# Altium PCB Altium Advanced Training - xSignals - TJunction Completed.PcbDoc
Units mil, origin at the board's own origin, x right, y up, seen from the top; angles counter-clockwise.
Board outline 4055.12 x 2100 mil, 3 copper layers (Top Layer, GND, Bottom Layer), stack 68.617 mil thick; 14 components, 11 nets, 32 pads, 2 vias.
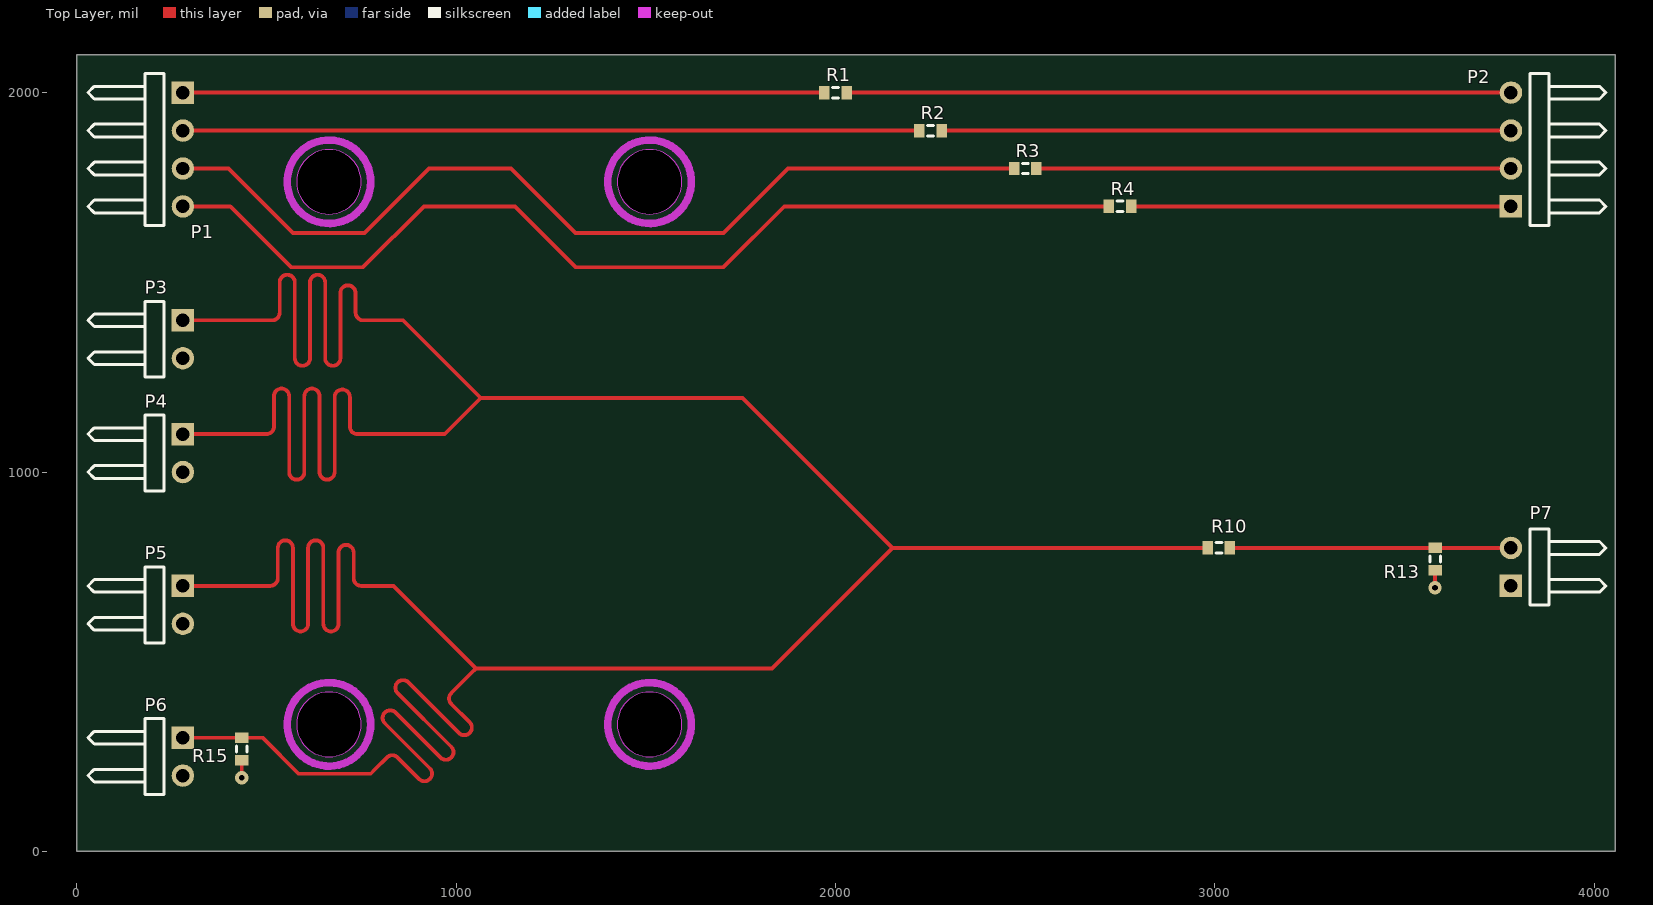
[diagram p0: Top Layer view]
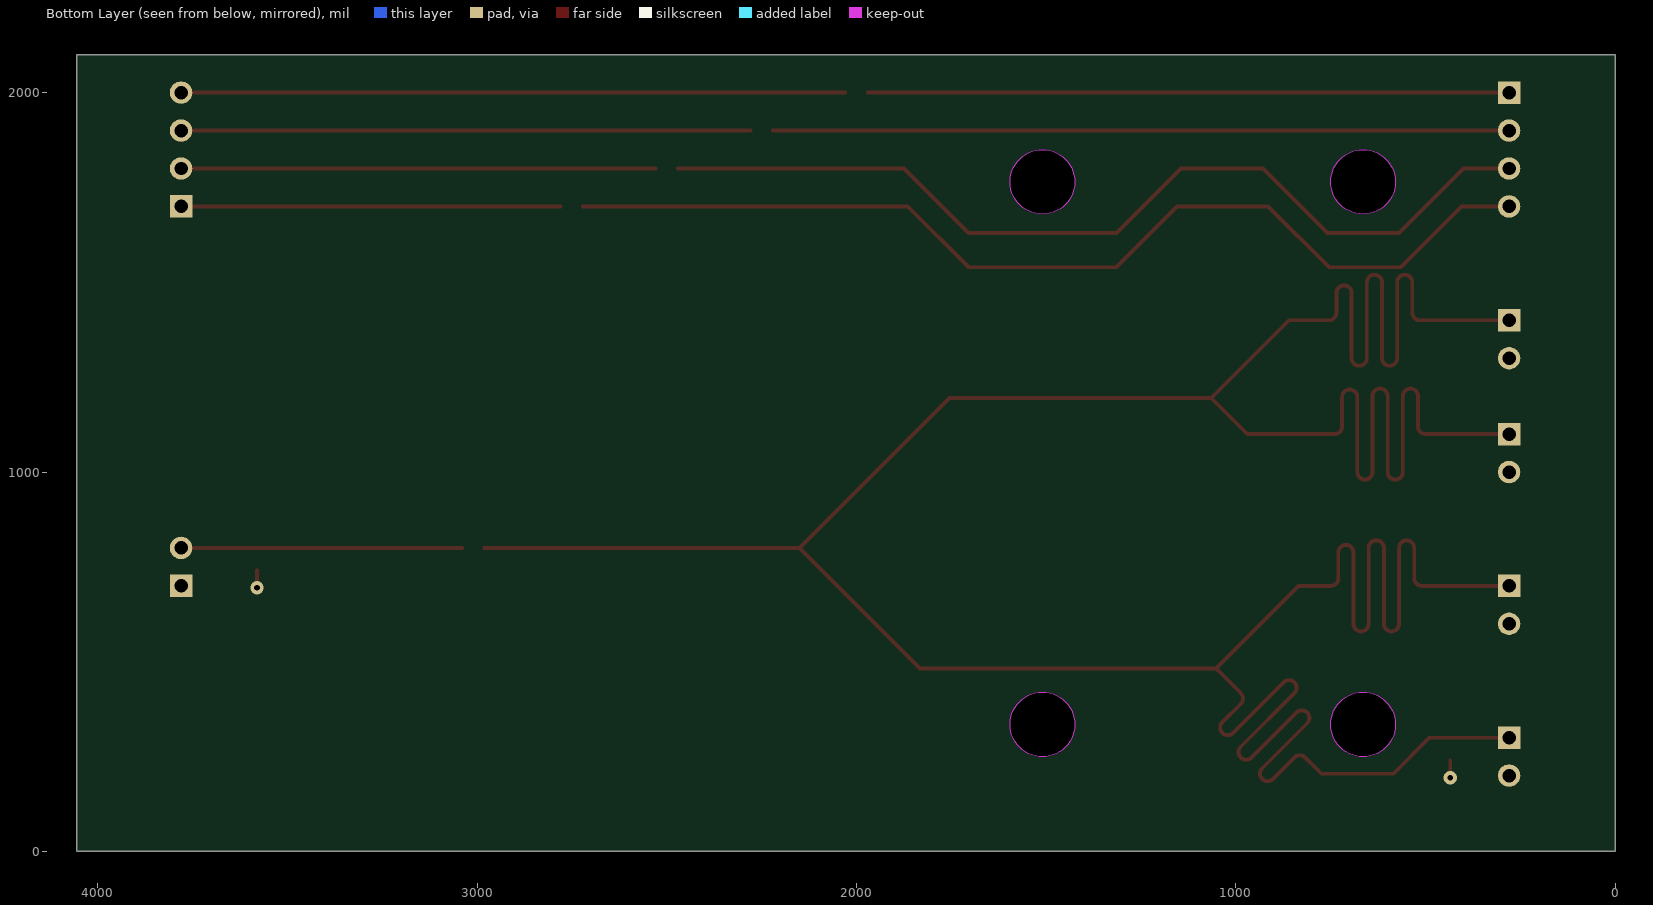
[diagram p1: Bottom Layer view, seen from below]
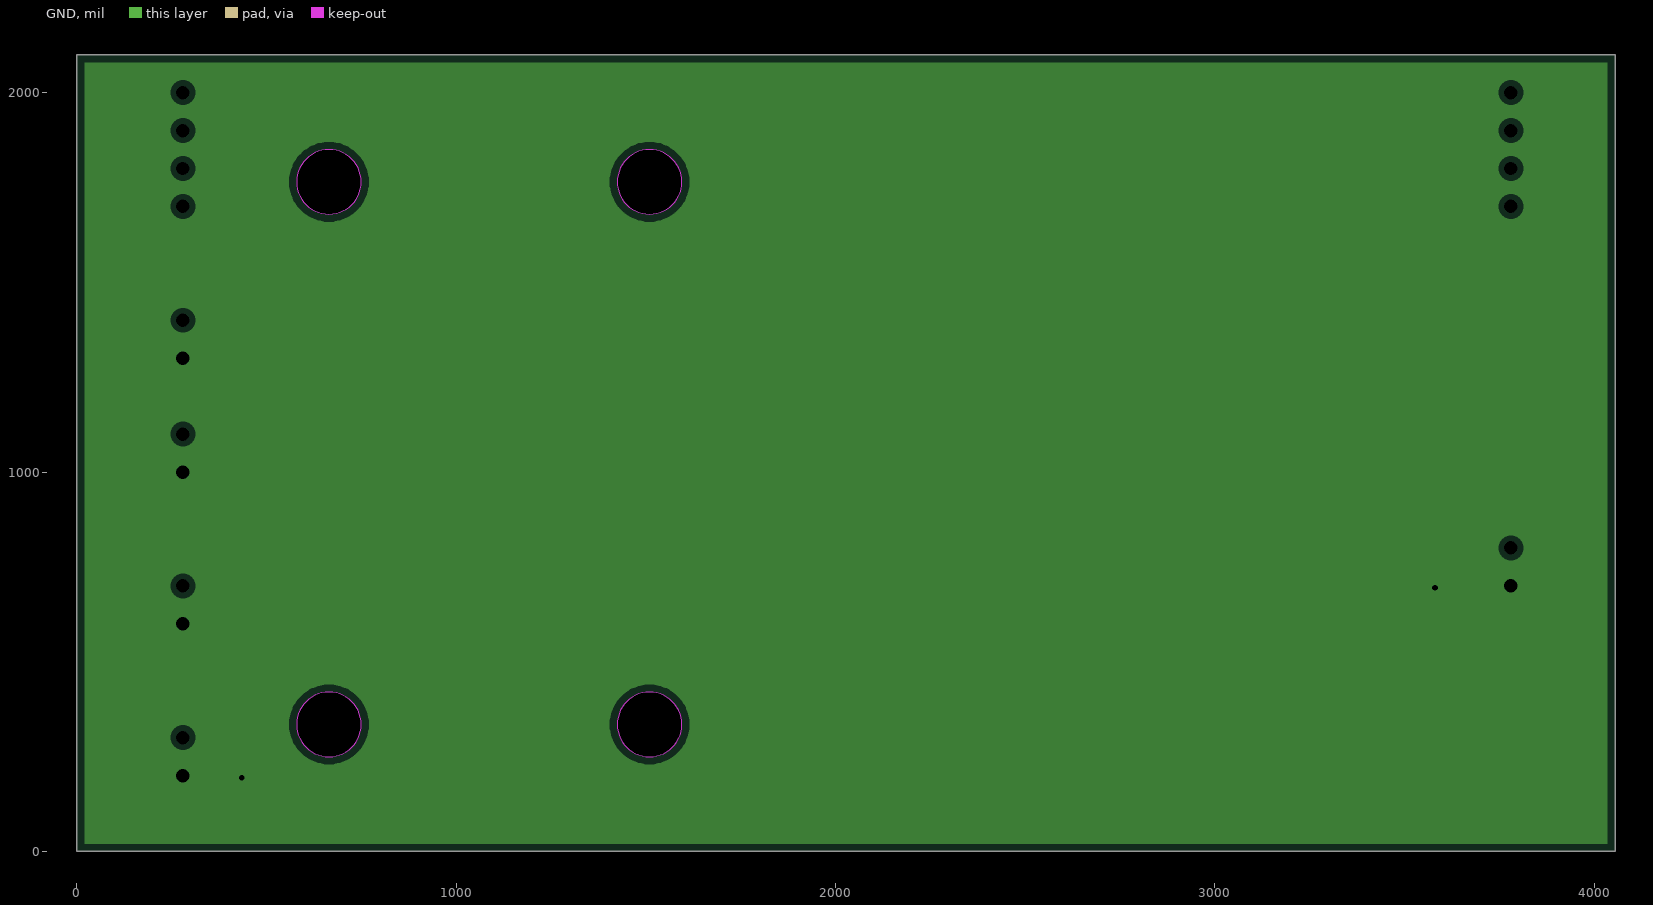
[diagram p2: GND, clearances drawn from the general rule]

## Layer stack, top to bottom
Top Solder: solder mask 0.4, Solder Resist, Dk 3.5
Top Layer: signal copper 1.4
Dielectric1: core 59.4, FR-4, Dk 4
GND: plane copper 1.417, net GND
Dielectric 2: prepreg 5, Dk 4.2
Bottom Layer: signal copper 1.4
Bottom Solder: solder mask 0.4, Solder Resist, Dk 3.5

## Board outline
0,0 4055.12,0 4055.12,2100 0,2100
cut-out: 579.65,334.79 ccw(c664.79,334.79) 664.79,249.65 ccw(c664.79,334.79) 749.94,334.79 ccw(c664.79,334.79) 664.79,419.94 ccw(c664.79,334.79)
cut-out: 579.65,1764.79 ccw(c664.79,1764.79) 664.79,1679.65 ccw(c664.79,1764.79) 749.94,1764.79 ccw(c664.79,1764.79) 664.79,1849.94 ccw(c664.79,1764.79)
cut-out: 1424.65,334.79 ccw(c1509.79,334.79) 1509.79,249.65 ccw(c1509.79,334.79) 1594.94,334.79 ccw(c1509.79,334.79) 1509.79,419.94 ccw(c1509.79,334.79)
cut-out: 1424.65,1764.79 ccw(c1509.79,1764.79) 1509.79,1679.65 ccw(c1509.79,1764.79) 1594.94,1764.79 ccw(c1509.79,1764.79) 1509.79,1849.94 ccw(c1509.79,1764.79)

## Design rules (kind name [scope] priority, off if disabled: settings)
AcuteAngle [All] p1: minimum=5.50000000000000E+0001 checktracksonly=FALSE
AssemblyTestPointUsage [All] p1 off:
AssemblyTestpoint [All] p1 off: testpointundercomponent=TRUE minsize=40 maxsize=100 preferedsize=60 minholesize=0 maxholesize=40 preferedholesize=32 testpointgrid=1 usegrid=TRUE gridtolerance=0.01 allowsidetop=TRUE allowsidebottom=TRUE
BoardOutlineClearance [All] p1: gap=10 ignorepadtopadclearanceinfootprint=FALSE except(0: Arc-SplitContinuation Track-SplitContinuation SMDPad-SplitContinuation THPad-SplitContinuation Via-SplitContinuation Fill-SplitContinuation Poly-SplitContinuation Region-SplitContinuation Text-SplitContinuation)
Clearance [All] p1: gap=8 ignorepadtopadclearanceinfootprint=FALSE except(0: Arc-Hole Track-Hole SMDPad-Hole THPad-Hole Via-Hole Fill-Hole Poly-Hole Region-Hole Text-Hole)
FabricationTestPointUsage [All] p1 off: valid=0 allowmultiple=FALSE
FabricationTestpoint [(IsPad And (OnTopLayer Or OnBottomLayer))] p1 off: side=3 testpointundercomponent=TRUE minsize=40 maxsize=100 preferedsize=60 minholesize=0 maxholesize=40 preferedholesize=32 testpointgrid=1 allowsidetop=TRUE allowsidebottom=TRUE usegrid=TRUE gridtolerance=0.01
Height [All] p1: minheight=0 maxheight=1500 prefheight=500
HoleSize [All] p1: absolutevalues=TRUE maxlimit=200 minlimit=10 maxpercent=80.000 minpercent=20.000
HoleToHoleClearance [All] p1: gap=1 allowstackedmicrovias=FALSE
Length Length_TJunction [InxSignalClass('T-Junction')] p1: maxlimit=4100 minlimit=3900
Length Length_Series-Term [InxSignalClass('Series-Term')] p2: maxlimit=3855 minlimit=3845
MatchedLengths MatchedLengths_TJunction [InxSignalClass('T-Junction')] p1: tolerance=10 checknetsindiffpair=FALSE checkdiffpairvsdiffpair=TRUE checkxsignals=TRUE checkothers=TRUE
MinimumAnnularRing [All] p1: minimumring=5
MinimumSolderMaskSliver [All] p1: minsoldermaskwidth=3
NetAntennae [All] p1: netantennaetolerance=5
PlaneClearance [All] p1: clearance=15
PlaneConnect [All] p1: planeconnectstyle=Relief reliefexpansion=15 reliefentries=4 reliefconductorwidth=8 reliefairgap=8
PolygonConnect [All] p1: connectstyle=Relief reliefconductorwidth=8 reliefentries=4 polygonreliefangle="90 Angle" airgapwidth=10
RoutingTopology RoutingTopology_TJUNCT [InNet('TJUNCT')] p1: topology=Starburst
RoutingTopology [All] p2: topology=Shortest
RoutingVias [All] p1: holewidth=10 width=20 viastyle="Through Hole" minholewidth=10 minwidth=20 maxholewidth=30 maxwidth=40
SilkToSilkClearance [All] p1: silktosilkclearance=1
SilkToSolderMaskClearance SilkscreenOverComponentPads [IsPad] p1: minsilkscreentomaskgap=2 clearancetoexposedcopper=TRUE
SolderMaskExpansion [All] p1: expansion=1 istentingtop=FALSE
Width [All] p1: maxlimit=200 minlimit=8 preferedwidth=10
16 further rules are at their usual default settings.

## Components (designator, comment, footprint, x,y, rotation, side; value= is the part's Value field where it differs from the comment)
P1 "Header 4H" HDR1X4H 280,2000 r270 top
P2 "Header 4H" HDR1X4H 3780,1700 r90 top
P3 "Header 2H" HDR1X2H 280,1400 r270 top
P4 "Header 2H" HDR1X2H 280,1100 r270 top
P5 "Header 2H" HDR1X2H 280,700 r270 top
P6 "Header 2H" HDR1X2H 280,300 r270 top
P7 "Header 2H" HDR1X2H 3780,700 r90 top
R1 "Res3" J1-0603 2000,2000 r180 top
R2 "Res3" J1-0603 2250,1900 r180 top
R3 "Res3" J1-0603 2500,1800 r180 top
R4 "Res3" J1-0603 2750,1700 r180 top
R10 "Res3" J1-0603 3010,800 r180 top
R13 "Res3" J1-0603 3580,770.47 r90 top
R15 "Res3" J1-0603 435,270 r90 top

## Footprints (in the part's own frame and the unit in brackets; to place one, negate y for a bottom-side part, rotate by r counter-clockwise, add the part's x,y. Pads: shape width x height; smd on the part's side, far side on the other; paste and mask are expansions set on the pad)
HDR1X2H [mm] "Connector; Header; 2 Position; Right Angle"
  rect 1.5x1.5 hole 0.9: 1(0,0)
  round 1.5 hole 0.9: 2(2.54,0)
  silkscreen extent -1.27,-6.35 3.81,-1.27
HDR1X4H [mm] "Connector; Header; 4 Position; Right Angle"
  rect 1.5x1.5 hole 0.9: 1(0,0)
  round 1.5 hole 0.9: 2(2.54,0) 3(5.08,0) 4(7.62,0)
  silkscreen extent -1.27,-6.35 8.89,-1.27
J1-0603 [mm] "Chip Resistor, Body 1.6x0.8mm, IPC High Density"
  rect 0.7x0.9 smd: 1(-0.75,0) 2(0.75,0)
  silkscreen extent -0.2,-0.35 0.2,0.35, body extent -0.85,-0.48 0.85,0.48, height 0.9

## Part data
P1 P2: "Header, 4-Pin, Right Angle"
P3 P4 P5 P6 P7: "Header, 2-Pin, Right Angle"
R1 R2 R3 R4 R10 R13 R15: "Resistor"

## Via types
v1: diameter 35, hole 15, Top Layer to Bottom Layer, 2 vias

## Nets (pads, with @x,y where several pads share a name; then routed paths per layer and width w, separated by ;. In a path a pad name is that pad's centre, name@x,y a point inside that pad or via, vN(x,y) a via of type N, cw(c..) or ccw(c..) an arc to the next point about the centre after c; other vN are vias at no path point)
BUS1: P1.1 R1.2 | length 1690.5
  Top Layer w10: P1.1 1050,2000 1510,2000 1569.77,2000 R1.2
BUS2: P1.2 R2.2 | length 1940.5
  Top Layer w10: P1.2 R2.2
BUS3: P1.3 R3.2 | length 2472.1
  Top Layer w10: P1.3 400,1800 570,1630 758.75,1630 928.75,1800 1145,1800 1315,1630 1705,1630 1875,1800 1937.5,1800 2235,1800 2285,1800 R3.2
BUS4: P1.4 R4.2 | length 2705.6
  Top Layer w10: P1.4 405,1700 565,1540 755,1540 915,1700 985,1700 1140,1700 1155,1700 1315,1540 1705,1540 1865,1700 2045,1700 2315,1700 R4.2
GND: P3.2 P4.2 P5.2 P6.2 P7.1 R13.1 R15.1 | length 91.9
  Top Layer w10: v1(435,194.53) R15.1 ; v1(3580,695) R13.1
OBUS1: P2.4 R1.1 | length 1750.5
  Top Layer w10: R1.1 2897.82,2000 P2.4
OBUS2: P2.3 R2.1 | length 1500.5
  Top Layer w10: R2.1 2540,1900 2720,1900 3225,1900 P2.3
OBUS3: P2.2 R3.1 | length 1250.5
  Top Layer w10: R3.1 P2.2
OBUS4: P2.1 R4.1 | length 1000.5
  Top Layer w10: R4.1 3271.89,1700 P2.1
TJSOURCE: P7.2 R10.1 R13.2 | length 740.5
  Top Layer w10: R10.1 R13.2 P7.2
TJUNCT: P3.1 P4.1 P5.1 P6.1 R10.2 R15.2 | length 11006.3
  Top Layer w10: P6.1 434.53,300 R15.2 435.47,300 490,300 585,205 775,205 785.78,215.78 817.6,247.6 cw(c831.75,233.46) 845.89,247.6 902.46,191.03 ccw(c916.6,205.18) 930.74,191.03 ccw(c916.6,205.18) 930.74,219.32 812.14,337.92 cw(c826.28,352.06) 812.14,366.2 cw(c826.28,352.06) 840.43,366.2 959.02,247.6 ccw(c973.17,261.75) 987.31,247.6 ccw(c973.17,261.75) 987.31,275.89 845.89,417.31 cw(c860.03,431.45) 845.89,445.59 cw(c860.03,431.45) 874.17,445.59 1007.21,312.56 ccw(c1021.35,326.7) 1035.49,312.56 ccw(c1021.35,326.7) 1035.49,340.84 987.31,389.02 cw(c1001.45,403.17) 987.31,417.31 1040,470 1052.5,482.5 ; P5.1 505,700 510,700 ccw(c510,720) 530,720 530,800 cw(c550,800) 570,800 570,600 ccw(c590,600) 610,600 610,800 cw(c630,800) 650,800 650,600 ccw(c670,600) 690,600 690,787.97 cw(c710,787.97) 730,787.97 730,720 ccw(c750,720) 750,700 795,700 835,700 1052.5,482.5 ; P4.1 495,1100 500,1100 ccw(c500,1120) 520,1120 520,1200 cw(c540,1200) 560,1200 560,1000 ccw(c580,1000) 600,1000 600,1200 cw(c620,1200) 640,1200 640,1000 ccw(c660,1000) 680,1000 680,1197.29 cw(c700,1197.29) 720,1197.29 720,1120 ccw(c740,1120) 740,1100 940,1100 970,1100 1065,1195 ; P3.1 510,1400 515,1400 ccw(c515,1420) 535,1420 535,1500 cw(c555,1500) 575,1500 575,1300 ccw(c595,1300) 615,1300 615,1500 cw(c635,1500) 655,1500 655,1300 ccw(c675,1300) 695,1300 695,1472 cw(c715,1472) 735,1472 735,1420 ccw(c755,1420) 755,1400 785,1400 860,1400 1065,1195 ; R10.2 2150,800 ; 1052.5,482.5 1832.5,482.5 2150,800 ; 1065,1195 1755,1195 2150,800

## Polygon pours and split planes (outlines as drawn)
GND on GND (split plane): 4035.02,20.1 20.1,20.1 20.1,2079.9 4035.02,2079.9

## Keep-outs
Top Layer:
  circle w20: c665,335 r110
  circle w20: c665,1765 r110
  circle w20: c1510,335 r110
  circle w20: c1510,1765 r110

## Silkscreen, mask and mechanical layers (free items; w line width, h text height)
Top Overlay:
  text "Altium Advanced Training: '.Pcb_File_Name_No_Path'" at 15,-251.68 h100
Mechanical 1:
  drawing of 211 lines, arcs and shapes, not listed
  text "Layer" at -5222.5,-212.5 h60
  text "Name" at -4874.26,-212.5 h60
  text "Material" at -4109.54,-212.5 h60
  text "Thickness" at -3447.08,-212.5 h60
  text "Constant" at -2933.16,-212.5 h60
  text "Board Layer Stack" at -2440.37,-212.5 h60
  text "Top Overlay" at -4874.26,-332.5 h60
  text "Top Solder" at -4874.26,-452.5 h60
  text "Solder Resist" at -4109.54,-452.5 h60
  text "0,40mil" at -3447.08,-452.5 h60
  text "3.5" at -2933.16,-452.5 h60
  text "1" at -5222.5,-572.5 h60
  text "Top Layer" at -4874.26,-572.5 h60
  text "1,40mil" at -3447.08,-572.5 h60
  text "Dielectric1" at -4874.26,-692.5 h60
  text "FR-4" at -4109.54,-692.5 h60
  text "59,40mil" at -3447.08,-692.5 h60
  text "4" at -2933.16,-692.5 h60
  text "2" at -5222.5,-812.5 h60
  text "GND" at -4874.26,-812.5 h60
  text "1,42mil" at -3447.08,-812.5 h60
  text "Dielectric 2" at -4874.26,-932.5 h60
  text "5,00mil" at -3447.08,-932.5 h60
  text "4.2" at -2933.16,-932.5 h60
  text "3" at -5222.5,-1052.5 h60
  text "Bottom Layer" at -4874.26,-1052.5 h60
  text "1,40mil" at -3447.08,-1052.5 h60
  text "Bottom Solder" at -4874.26,-1172.5 h60
  text "Solder Resist" at -4109.54,-1172.5 h60
  text "0,40mil" at -3447.08,-1172.5 h60
  text "3.5" at -2933.16,-1172.5 h60
  text "Bottom Overlay" at -4874.26,-1292.5 h60
Mechanical 16:
  lines w5: -5810.13,-1827.43 -5610.13,-1827.43 ; -5810.13,547.57 -5610.13,547.57 ; -5810.13,2922.57 -5610.13,2922.57 ; -3310.13,-4202.43 -3310.13,-4002.43 ; -3310.13,5097.57 -3310.13,5297.57 ; -810.13,-4202.43 -810.13,-4002.43 ; -810.13,5097.57 -810.13,5297.57 ; 1536.87,-4002.43 1536.87,-3207.43 ; 1689.87,-4202.43 1689.87,-4002.43 ; 1689.87,5097.57 1689.87,5297.57 ; 3089.87,-3207.43 1536.87,-3207.43 ; 3089.87,-2934.43 1536.87,-2934.43 1536.87,-3207.43 ; 4189.87,-4202.43 4189.87,-4002.43 ; 4189.87,5097.57 4189.87,5297.57 ; 4489.87,-3702.43 8989.87,-3702.43 ; 4489.87,-3402.43 8989.87,-3402.43 ; 4489.87,-3102.43 5989.87,-3102.43 ; 5989.72,-4002.28 5989.72,-3402.28 5989.72,-2802.28 8989.72,-2802.28 8989.72,-4002.28 ; 5989.87,-2802.43 4489.87,-2802.43 ; 6613.21,-4202.75 6613.21,-4002.75 ; 6689.87,-4202.43 6689.87,-4002.43 ; 6689.87,5097.57 6689.87,5297.57 ; 7259.72,-4002.28 7259.72,-3702.28 ; 8089.72,-4002.28 8089.72,-3402.28 ; 8989.87,-1827.43 9189.87,-1827.43 ; 8989.87,547.57 9189.87,547.57 ; 8989.87,2922.57 9189.87,2922.57 ; 4489.87,-4002.43 4489.87,-2802.43 ; 4489.87,-4002.43 8989.87,-4002.43 ; 4489.87,-4002.43 3089.87,-4002.43 3089.87,-2802.43 4489.87,-2802.43 ; 8989.87,-4002.43 8989.87,5097.57 -5610.13,5097.57 -5610.13,-4002.43 8989.87,-4002.43 ; -5810.13,-4202.43 -5810.13,5297.57 9189.87,5297.57 9189.87,-4202.43 -5810.13,-4202.43
  lines w10: 6539.87,4817.57 6539.87,4892.57 6539.87,4957.57 6539.87,5032.57 6539.87,5097.57 ; 6540,4817.57 8989.87,4817.57 ; 6540,4892.57 8989.87,4892.57 8989.87,5032.57 ; 6540,4957.57 8989.87,4957.57 ; 6540,5032.57 8989.87,5032.57 ; 6540,5097.57 8989.87,5097.57 8989.87,5032.57 ; 6684.87,4817.76 6684.87,5032.57 ; 7014.87,4817.76 7014.87,5032.57 ; 8419.87,4817.76 8419.87,5032.57 ; 8689.87,4817.76 8689.87,5032.57
  text "1" at -4578.79,5167.57 h70
  text "2" at -2083.13,5167.57 h70
  text "3" at 406.21,5167.57 h70
  text "4" at 2912.88,5167.57 h70
  text "5" at 5411.87,5167.57 h70
  text "6" at 7916.87,5167.57 h70
  text "REVISIONS" at 7642,5051.76 h30
  text "DESCRIPTION" at 7630,4980.76 h30
  text "REV" at 6564.87,4977.57 h30
  text "ECO#/ECR#" at 6724.87,4977.57 h30
  text "APPROV" at 8454.87,4977.57 h30
  text "DATE" at 8794.87,4977.57 h30
  text "01" at 6584.87,4912.57 h30
  text "INITIAL RELEASE" at 7054.87,4912.57 h30
  text "10/31/11" at 8734.87,4912.57 h30
  text "A" at -5735.13,4024.57 h70
  text "A" at 9064.87,4024.57 h70
  text "B" at -5735.13,1644.57 h70
  text "B" at 9064.87,1644.57 h70
  text "C" at -5735.13,-730.43 h70
  text "C" at 9064.87,-730.43 h70
  text "ENGINEER:" at 4539.87,-2902.43 h45
  text "TITLE:" at 6039.72,-2902.28 h45
  text "<YOUR NAME>" at 4646.87,-3053.43 h80
  text "Company" at 3158,-3074.24 h140
  text "D" at -5735.13,-3100.43 h70
  text "D" at 9064.87,-3100.43 h70
  text "PCB DESIGNER:" at 4539.87,-3197.43 h45
  text "UNLESS OTHERWISE SPECIFIED" at 1626.87,-3313.43 h55.31
  text "<YOUR NAME>" at 4644.87,-3376.43 h80
  text "DIMINSIONS ARE IN INCHES." at 1626.87,-3401.43 h55.31
  text "LAYER" at 6040.72,-3475.28 h45
  text "DATE:" at 4539.87,-3502.43 h45
  text "REV:" at 8139.72,-3502.28 h45
  text "TOLERANCES ARE:" at 1954.87,-3580.43 h55.31
  text ".PRINT_DATE" at 4589.87,-3622.43 h70
  text "01" at 8474.72,-3636.3 h130
  text "100 Main Street" at 3126.5,-3638.02 h56.25
  text "DECIMALS" at 1616.87,-3704.43 h55.31
  text "ANGLES" at 2576.87,-3720.43 h55.31
  text "AnytownUSA, CA 12345" at 3124.37,-3734.35 h56.25
  text "SHT NO:" at 7280.72,-3792.28 h45
  text ".XX  +/- .01" at 1612.87,-3800.43 h55.31
  text "FILE NAME:" at 4539.87,-3802.43 h45
  text "DWG NO:" at 6039.72,-3802.28 h45
  text "SCALE:" at 8139.72,-3802.28 h45
  text "+/- .5 DEG" at 2456.87,-3817.43 h55.31
  text "Phone: (123) 555-1212" at 3122.21,-3832.82 h55.31
  text ".XXX +/- .003" at 1612.87,-3906.43 h55.31
  text "name@company.com" at 3122.21,-3914.2 h56.25
  text ".PCB_FILE_NAME_NO_PATH" at 4589.83,-3922.38 h70
  text ".PCB_FILE_NAME_NO_PATH" at 4589.87,-3922.43 h70
  text "N/A" at 8414.72,-3926.28 h130
  text "of" at 7661.67,-3949.61 h75
  text "1" at -4578.79,-4132.43 h70
  text "2" at -2083.13,-4132.43 h70
  text "3" at 406.21,-4132.43 h70
  text "4" at 2912.88,-4132.43 h70
  text "5" at 5411.87,-4132.43 h70
  text "4" at 7916.72,-4132.28 h70
Drill Drawing:
  circle w10: c-5248.98,-3104.28 r26.94
  lines w10: -5275.92,-3252.42 -5222.05,-3252.42 -5222.05,-3198.55 -5275.92,-3198.55 -5275.92,-3252.42
  lines w15: -5324.83,-3288.79 1089.13,-3288.79 ; -5324.83,-3046.36 1089.13,-3046.36 ; -4873.54,-3410 -4873.54,-2925.15 ; -4433.45,-3410 -4433.45,-2925.15 ; -3524.83,-3410 -3524.83,-2925.15 ; -3109.91,-3410 -3109.91,-2925.15 ; -2510.8,-3410 -2510.8,-2925.15 ; -1295.21,-3410 -1295.21,-2925.15 ; -812.42,-3410 -812.42,-2925.15 ; -203.62,-3410 -203.62,-2925.15 ; 453.65,-3410 453.65,-2925.15 ; -5324.83,-3410 1089.13,-3410 1089.13,-2925.15 -5324.83,-2925.15 -5324.83,-3410
  text "Symbol" at -5252.11,-3010 h58.18
  text "Count" at -4837.18,-3010 h58.18
  text "Hole Size" at -4397.09,-3010 h58.18
  text "Plated" at -3488.47,-3010 h58.18
  text "Hole Type" at -3073.54,-3010 h58.18
  text "Drill Layer Pair" at -2474.43,-3010 h58.18
  text "Via/Pad" at -1258.84,-3010 h58.18
  text "Pad Shape" at -776.06,-3010 h58.18
  text "Technology" at -167.26,-3010 h58.18
  text "Tolerance" at 490.02,-3010 h58.18
  text "2" at -4837.18,-3131.21 h48.48
  text "15,00mil (0,381mm)" at -4397.09,-3131.21 h48.48
  text "PTH" at -3488.47,-3131.21 h48.48
  text "Round" at -3073.54,-3131.21 h48.48
  text "Top Layer - Bottom Layer" at -2474.43,-3131.21 h48.48
  text "Via" at -1258.84,-3131.21 h48.48
  text "Rounded" at -776.06,-3131.21 h48.48
  text "v89h38" at -167.26,-3131.21 h48.48
  text "18" at -4837.18,-3252.42 h48.48
  text "35,43mil (0,900mm)" at -4397.09,-3252.42 h48.48
  text "PTH" at -3488.47,-3252.42 h48.48
  text "Round" at -3073.54,-3252.42 h48.48
  text "Top Layer - Bottom Layer" at -2474.43,-3252.42 h48.48
  text "Pad" at -1258.84,-3252.42 h48.48
  text "(Mixed)" at -776.06,-3252.42 h48.48
  text "(Mixed)" at -167.26,-3252.42 h48.48
  text "20 Total" at -4837.18,-3373.63 h48.48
